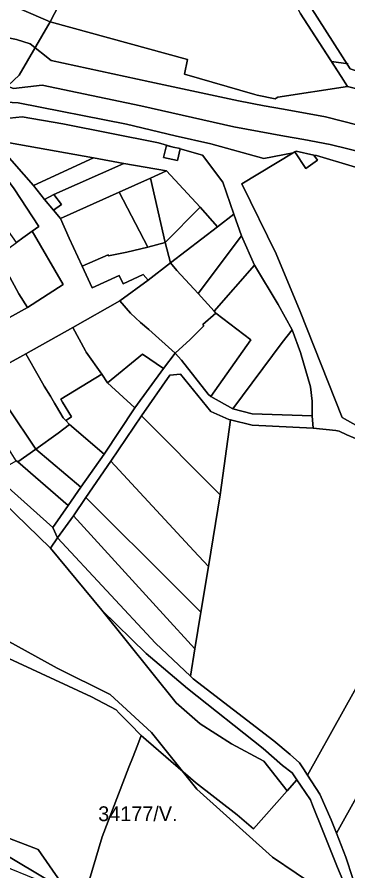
# Model space of a CAD drawing. Extents: x -545779 to -541342, y -1153413 to -1149956.
# Drawn here: x -543702.6 to -543590.9, y -1151443.3 to -1151154.8 of the extents above; entities that cross this region are included whole.
import ezdxf

# ---------------------------------------------------------------- set-up
doc = ezdxf.new("R2010")
doc.units = 0
for name, color, linetype in [('95560013', 7, 'Continuous'), ('95590013', 7, 'Continuous'), ('95600013', 7, 'Continuous'), ('95610013', 7, 'Continuous'), ('95630013', 7, 'Continuous'), ('95640013', 7, 'Continuous'), ('95660013', 7, 'Continuous')]:
    doc.layers.add(name, color=color, linetype=linetype)

msp = doc.modelspace()

# ---------------------------------------------------------------- linework, layer by layer
at = {"layer": '95560013'}
for points in [[(-543426.69, -1151032.45), (-543416.26, -1151059.6), (-543408.67, -1151071.25), (-543550.86, -1151185.35), (-543553.59, -1151184.67), (-543590.14, -1151172.28), (-543603.89, -1151150.79), (-543516.57, -1151080.72), (-543429.25, -1151010.65)], [(-543691.29, -1151334.17), (-543673.94, -1151355.22), (-543648.95, -1151386.43), (-543640.79, -1151393.58), (-543630.21, -1151400.33), (-543619.37, -1151406.18), (-543611.49, -1151416.21), (-543622.76, -1151429.01), (-543628.36, -1151424.32), (-543642.34, -1151413.36), (-543660.7, -1151397.48), (-543664.49, -1151393.61), (-543664.86, -1151393.23), (-543668.09, -1151389.92), (-543669.09, -1151388.9), (-543677.42, -1151384.4), (-543739.44, -1151355.73), (-543734.37, -1151340.55), (-543723.18, -1151345.39), (-543718.04, -1151333.17), (-543708.47, -1151320.29), (-543707.2, -1151318.74)], [(-543551.98, -1151332.36), (-543550.87, -1151334.45), (-543548.07, -1151339.72), (-543546.41, -1151342.35), (-543546.06, -1151342.91), (-543594.77, -1151430.54), (-543596.55, -1151425.99), (-543600.47, -1151417.38), (-543604.56, -1151410.97), (-543556.48, -1151324.47), (-543555.16, -1151326.78)], [(-543546.06, -1151342.91), (-543543.88, -1151346.35), (-543541.07, -1151350.8), (-543534.97, -1151358.76), (-543586.01, -1151450.59), (-543589.23, -1151445.86), (-543591.62, -1151438.6), (-543594.77, -1151430.54)]]:
    msp.add_lwpolyline(points, close=True, dxfattribs=at)
msp.add_lwpolyline([(-543556.48, -1151324.47), (-543604.56, -1151410.97), (-543605.95, -1151408.8), (-543607.27, -1151406.73), (-543610.39, -1151403.99), (-543615.92, -1151399.29), (-543643.15, -1151378.33), (-543644.09, -1151377.44), (-543642.58, -1151368.24), (-543640.56, -1151355.87), (-543638.03, -1151340.4), (-543634.06, -1151316.17), (-543630.6, -1151290.91), (-543623.22, -1151292.69), (-543602.72, -1151293.72), (-543595.06, -1151294.52), (-543593.88, -1151294.64), (-543591.36, -1151295.92), (-543582.77, -1151299.49)], dxfattribs=at)
at = {"layer": '95590013'}
for points in [[(-543707.45, -1151199.51), (-543705.09, -1151197.25), (-543676.75, -1151202.34), (-543696.99, -1151211.72), (-543707.61, -1151199.67)], [(-543690.15, -1151214.69), (-543693.35, -1151216.4), (-543696.99, -1151211.72), (-543676.75, -1151202.34), (-543666.57, -1151204.23)], [(-543657.58, -1151209.21), (-543668.11, -1151213.94), (-543687.97, -1151222.83), (-543690.31, -1151219.98), (-543687.61, -1151218.1), (-543690.15, -1151214.69), (-543666.57, -1151204.23), (-543652.11, -1151206.75)], [(-543657.58, -1151209.21), (-543652.11, -1151206.75), (-543640.81, -1151219.02), (-543652.58, -1151230.91)], [(-543658.5, -1151232.51), (-543668.11, -1151213.94), (-543657.58, -1151209.21), (-543652.58, -1151230.91)], [(-543640.81, -1151219.02), (-543634.91, -1151225.67), (-543650.86, -1151237.82), (-543652.58, -1151230.91)], [(-543650.86, -1151237.82), (-543634.91, -1151225.67), (-543629.48, -1151221.37), (-543626.8, -1151228.65), (-543641.53, -1151248.13), (-543648.65, -1151240.41)], [(-543613.18, -1151264.7), (-543609.74, -1151260.46), (-543606.96, -1151268.13), (-543603.6, -1151279.66), (-543603.04, -1151284.54), (-543603.04, -1151289.47), (-543623.3, -1151288.83), (-543629.79, -1151287.1)], [(-543660.31, -1151268.64), (-543653.13, -1151273.5), (-543662.86, -1151286.76), (-543672.1, -1151278.36)], [(-543662.86, -1151286.76), (-543673.25, -1151302.44), (-543684.87, -1151292.42), (-543686.16, -1151291.06), (-543684.23, -1151289.85), (-543687.24, -1151284.9), (-543687.86, -1151283.9), (-543673.96, -1151275.39), (-543672.1, -1151278.36)], [(-543631.15, -1151290.78), (-543630.6, -1151290.91), (-543634.06, -1151316.17), (-543634.47, -1151315.75), (-543660.58, -1151289.47), (-543651.02, -1151275.79), (-543647.44, -1151275.49), (-543637.15, -1151288.1)], [(-543634.47, -1151315.75), (-543634.06, -1151316.17), (-543638.03, -1151340.4), (-543642.93, -1151335.1), (-543670.97, -1151304.78), (-543660.58, -1151289.47)], [(-543684.87, -1151292.42), (-543673.25, -1151302.44), (-543681.02, -1151313.61), (-543696.27, -1151300.72), (-543688.77, -1151295.37)], [(-543696.27, -1151300.72), (-543681.02, -1151313.61), (-543685.3, -1151319.77), (-543702.38, -1151305.07)], [(-543702.87, -1151304.68), (-543702.38, -1151305.07), (-543685.3, -1151319.77), (-543690.49, -1151327.2), (-543709.95, -1151309.86), (-543710.37, -1151308.95)], [(-543638.03, -1151340.4), (-543640.56, -1151355.87), (-543648.94, -1151347.49), (-543679.35, -1151317.1), (-543670.97, -1151304.78), (-543642.93, -1151335.1)], [(-543648.94, -1151347.49), (-543640.56, -1151355.87), (-543642.58, -1151368.24), (-543653.3, -1151356.49), (-543683.56, -1151323.3), (-543679.35, -1151317.1)], [(-543688.98, -1151330.77), (-543688.08, -1151329.53), (-543683.56, -1151323.3), (-543653.3, -1151356.49), (-543642.58, -1151368.24), (-543644.09, -1151377.44), (-543655.85, -1151366.32)]]:
    msp.add_lwpolyline(points, close=True, dxfattribs=at)
at = {"layer": '95600013'}
msp.add_lwpolyline([(-543664.49, -1151393.61), (-543660.7, -1151397.48), (-543661.86, -1151400.51), (-543663.64, -1151405.14), (-543664.82, -1151408.21), (-543673.88, -1151431.71), (-543679.37, -1151450.34), (-543682.23, -1151449.41), (-543683.51, -1151448.99), (-543692.85, -1151445.93), (-543769.18, -1151400.33), (-543759.62, -1151391.46), (-543753.2, -1151381.33), (-543752.52, -1151379.28), (-543751.06, -1151374.9), (-543743.07, -1151354.05), (-543739.44, -1151355.73), (-543677.42, -1151384.4), (-543669.09, -1151388.9), (-543668.09, -1151389.92), (-543664.86, -1151393.23)], close=True, dxfattribs=at)
at = {"layer": '95610013'}
msp.add_lwpolyline([(-543633.18, -1151210.51), (-543629.48, -1151221.37), (-543634.91, -1151225.67), (-543640.81, -1151219.02), (-543652.11, -1151206.75), (-543666.57, -1151204.23), (-543676.75, -1151202.34), (-543705.09, -1151197.25), (-543712.86, -1151196.79), (-543710.44, -1151192.02), (-543709.48, -1151189.44), (-543700.87, -1151188.52), (-543687.14, -1151190.91), (-543654.84, -1151197.32), (-543649.92, -1151198.7), (-543652.18, -1151198.19), (-543653.23, -1151202.2), (-543648.48, -1151203.27), (-543647.59, -1151199.35), (-543639.96, -1151201.49)], close=True, dxfattribs=at)
msp.add_lwpolyline([(-543679.37, -1151450.34), (-543673.88, -1151431.71), (-543664.82, -1151408.21), (-543663.64, -1151405.14), (-543661.86, -1151400.51), (-543660.7, -1151397.48), (-543642.34, -1151413.36), (-543628.36, -1151424.32), (-543622.76, -1151429.01), (-543611.49, -1151416.21), (-543608.2, -1151412.48), (-543607, -1151414.28), (-543603.62, -1151419.3), (-543602.89, -1151421.09), (-543599.41, -1151429.72), (-543594.46, -1151442.1), (-543591.78, -1151448.59)], dxfattribs=at)
at = {"layer": '95630013'}
for points in [[(-543904.45, -1151081.5), (-543875.92, -1151102.77), (-543852.01, -1151119.39), (-543836.64, -1151127.19), (-543820.44, -1151131.33), (-543791.01, -1151135.61), (-543774.37, -1151139.55), (-543759.44, -1151144.59), (-543728.11, -1151156.46), (-543704.49, -1151161.98), (-543702.79, -1151162.38), (-543698.15, -1151163.86), (-543691.06, -1151169.41), (-543657.83, -1151176.71), (-543627.82, -1151183.14), (-543619.19, -1151184.73), (-543612.66, -1151185.94), (-543598.49, -1151188.54), (-543548.68, -1151201.25)], [(-543551.46, -1151209.01), (-543596.99, -1151197.82), (-543605.86, -1151196.19), (-543612.4, -1151194.99), (-543629.42, -1151191.86), (-543660.77, -1151184.75), (-543694.1, -1151177.77), (-543703.84, -1151178.88), (-543707.99, -1151177.29), (-543709.68, -1151176.38), (-543730.51, -1151165.23), (-543762.49, -1151152.65), (-543776.19, -1151147.43), (-543792.55, -1151143.69), (-543819.74, -1151138.33), (-543838.2, -1151135.78), (-543856.8, -1151126.79), (-543880.87, -1151109.45), (-543909.38, -1151087.89)]]:
    msp.add_lwpolyline(points, dxfattribs=at)
at = {"layer": '95640013'}
for points in [[(-543914.79, -1151053.54), (-543883.76, -1151079.27), (-543853.83, -1151099.45), (-543832.05, -1151111.38), (-543803.43, -1151116.87), (-543766.25, -1151127.49), (-543729.27, -1151141.61), (-543705.29, -1151150.15), (-543703.3, -1151146.24), (-543702.64, -1151146.72), (-543700.92, -1151151.1), (-543701.13, -1151152.25), (-543691.46, -1151156.42), (-543645.1, -1151169.14), (-543646.12, -1151174.04), (-543622.39, -1151180.97), (-543621.56, -1151181.15), (-543615.46, -1151182.44), (-543615.13, -1151182.21), (-543614.55, -1151181.8), (-543591.06, -1151178.24), (-543474.99, -1151206.7)], [(-543548.68, -1151201.25), (-543598.49, -1151188.54), (-543612.66, -1151185.94), (-543619.19, -1151184.73), (-543627.82, -1151183.14), (-543657.83, -1151176.71), (-543691.06, -1151169.41), (-543698.15, -1151163.86), (-543702.79, -1151162.38), (-543704.49, -1151161.98), (-543728.11, -1151156.46), (-543759.44, -1151144.59), (-543774.37, -1151139.55), (-543791.01, -1151135.61), (-543820.44, -1151131.33), (-543836.64, -1151127.19), (-543852.01, -1151119.39), (-543875.92, -1151102.77), (-543904.45, -1151081.5)], [(-543909.38, -1151087.89), (-543880.87, -1151109.45), (-543856.8, -1151126.79), (-543838.2, -1151135.78), (-543819.74, -1151138.33), (-543792.55, -1151143.69), (-543776.19, -1151147.43), (-543762.49, -1151152.65), (-543730.51, -1151165.23), (-543709.68, -1151176.38), (-543707.99, -1151177.29), (-543703.84, -1151178.88), (-543694.1, -1151177.77), (-543660.77, -1151184.75), (-543629.42, -1151191.86), (-543612.4, -1151194.99), (-543605.86, -1151196.19), (-543596.99, -1151197.82), (-543551.46, -1151209.01)], [(-543607.02, -1151153.49), (-543593.23, -1151174.88), (-543591.06, -1151178.24), (-543614.55, -1151181.8), (-543615.13, -1151182.21), (-543615.46, -1151182.44), (-543621.56, -1151181.15), (-543622.39, -1151180.97), (-543646.12, -1151174.04), (-543645.1, -1151169.14), (-543691.46, -1151156.42), (-543682.89, -1151139.83)], [(-543553.4, -1151215.92), (-543601.53, -1151201.58), (-543602.42, -1151201.39), (-543608.46, -1151200.09), (-543608.87, -1151200.33), (-543609.43, -1151200.65), (-543619.29, -1151202.61), (-543637.18, -1151197.56), (-543649.23, -1151194.95), (-543665.68, -1151191), (-543702.17, -1151183.73), (-543706.27, -1151183.57), (-543710.63, -1151183.4), (-543714.64, -1151182), (-543722.54, -1151178.99), (-543736.15, -1151174.3), (-543749.75, -1151169.5), (-543763.41, -1151164.4), (-543777, -1151159.58), (-543787.4, -1151156.11), (-543798.93, -1151152.89)], [(-543706.27, -1151183.57), (-543702.17, -1151183.73), (-543665.68, -1151191), (-543649.23, -1151194.95), (-543637.18, -1151197.56), (-543619.29, -1151202.61), (-543609.43, -1151200.65), (-543626.78, -1151211.1), (-543615.15, -1151234.83), (-543607.08, -1151254.31), (-543592.86, -1151290.06), (-543564.09, -1151306.26)], [(-543582.77, -1151299.49), (-543591.36, -1151295.92), (-543593.88, -1151294.64), (-543595.06, -1151294.52), (-543602.72, -1151293.72), (-543603.04, -1151289.47), (-543603.04, -1151284.54), (-543603.6, -1151279.66), (-543606.96, -1151268.13), (-543609.74, -1151260.46), (-543614.45, -1151251.92), (-543622.45, -1151238.56), (-543626.8, -1151228.65), (-543629.48, -1151221.37), (-543633.18, -1151210.51), (-543639.96, -1151201.49), (-543647.59, -1151199.35), (-543647.56, -1151199.23), (-543649.92, -1151198.7), (-543654.84, -1151197.32), (-543687.14, -1151190.91), (-543700.87, -1151188.52), (-543709.48, -1151189.44)], [(-543707.61, -1151199.67), (-543696.99, -1151211.72), (-543693.35, -1151216.4), (-543690.31, -1151219.98), (-543687.97, -1151222.83), (-543684.97, -1151229.45), (-543680.64, -1151238.98), (-543677.28, -1151246.3), (-543668.09, -1151242.1), (-543666.73, -1151244.88), (-543660.02, -1151241.79), (-543658.4, -1151243.65), (-543667.96, -1151250.69), (-543683.79, -1151259.72), (-543699.65, -1151268.52), (-543712.31, -1151275.52)], [(-543564.09, -1151306.26), (-543592.86, -1151290.06), (-543607.08, -1151254.31), (-543615.15, -1151234.83), (-543626.78, -1151211.1), (-543609.43, -1151200.65), (-543608.87, -1151200.33), (-543608.46, -1151200.09), (-543602.42, -1151201.39), (-543601.53, -1151201.58), (-543553.4, -1151215.92)], [(-543709.95, -1151309.86), (-543690.49, -1151327.2), (-543688.98, -1151330.77), (-543691.29, -1151334.17), (-543707.2, -1151318.74)], [(-543591.78, -1151448.59), (-543594.46, -1151442.1), (-543599.41, -1151429.72), (-543602.89, -1151421.09), (-543603.62, -1151419.3), (-543607, -1151414.28), (-543608.2, -1151412.48), (-543609.8, -1151410.1), (-543612.97, -1151407.6), (-543619.54, -1151401.93), (-543645.13, -1151381.61), (-543659.01, -1151369.77), (-543673.94, -1151355.22), (-543691.29, -1151334.17), (-543688.98, -1151330.77), (-543655.85, -1151366.32), (-543644.09, -1151377.44), (-543643.15, -1151378.33), (-543615.92, -1151399.29), (-543610.39, -1151403.99), (-543607.27, -1151406.73), (-543605.95, -1151408.8), (-543604.56, -1151410.97), (-543600.47, -1151417.38), (-543596.55, -1151425.99), (-543594.77, -1151430.54), (-543591.62, -1151438.6), (-543589.23, -1151445.86)]]:
    msp.add_lwpolyline(points, dxfattribs=at)
for points in [[(-543591.06, -1151178.24), (-543593.23, -1151174.88), (-543607.02, -1151153.49), (-543634.9, -1151097.4), (-543628.2, -1151092.28), (-543630.2, -1151097.88), (-543624.3, -1151109.73), (-543603.89, -1151150.79), (-543590.14, -1151172.28), (-543553.59, -1151184.67), (-543550.86, -1151185.35), (-543521.25, -1151192.65), (-543475.14, -1151204.03), (-543448.24, -1151210.67), (-543423.83, -1151216.7), (-543340.81, -1151237.2), (-543325.56, -1151240.65), (-543225.5, -1151263.28), (-543213.98, -1151267.2), (-543204.67, -1151270.37), (-543341.53, -1151239.59), (-543425.84, -1151218.75), (-543474.99, -1151206.7)], [(-543690.45, -1151132.16), (-543682.89, -1151139.83), (-543691.46, -1151156.42), (-543701.13, -1151152.25), (-543699.75, -1151148.74)], [(-543649.92, -1151198.7), (-543647.56, -1151199.23), (-543647.59, -1151199.35), (-543648.48, -1151203.27), (-543653.23, -1151202.2), (-543652.18, -1151198.19)], [(-543687.02, -1151245.12), (-543697.47, -1151227.07), (-543695.27, -1151225.57), (-543703.52, -1151212.82), (-543704.8, -1151211.08), (-543707.93, -1151206.67), (-543715.75, -1151213.76), (-543722.05, -1151219.55), (-543734.92, -1151231.03), (-543745.16, -1151239.53), (-543747.71, -1151241.69), (-543746.82, -1151242.67), (-543743.07, -1151247.07), (-543743.22, -1151247.62), (-543735.7, -1151253.66), (-543732.87, -1151256.11), (-543729.14, -1151259.03), (-543729.01, -1151258.86), (-543723.13, -1151265.27), (-543711.35, -1151259.67), (-543699.04, -1151252.91)], [(-543707.93, -1151206.67), (-543704.8, -1151211.08), (-543703.52, -1151212.82), (-543695.27, -1151225.57), (-543697.47, -1151227.07), (-543700.61, -1151229.38), (-543702.77, -1151230.98), (-543708.21, -1151223.27), (-543712.06, -1151217.91), (-543715.75, -1151213.76)], [(-543693.35, -1151216.4), (-543690.15, -1151214.69), (-543687.61, -1151218.1), (-543690.31, -1151219.98)], [(-543665.56, -1151234.23), (-543671.68, -1151235.44), (-543671.8, -1151235.17), (-543680.64, -1151238.98), (-543684.97, -1151229.45), (-543687.97, -1151222.83), (-543668.11, -1151213.94), (-543658.5, -1151232.51)], [(-543705.31, -1151232.84), (-543702.77, -1151230.98), (-543700.61, -1151229.38), (-543697.47, -1151227.07), (-543687.02, -1151245.12), (-543699.04, -1151252.91), (-543702.04, -1151248.25), (-543708.93, -1151235.56)], [(-543636.05, -1151254.17), (-543641.53, -1151248.13), (-543626.8, -1151228.65), (-543622.45, -1151238.56)], [(-543650.86, -1151237.82), (-543658.4, -1151243.65), (-543660.02, -1151241.79), (-543666.73, -1151244.88), (-543668.09, -1151242.1), (-543677.28, -1151246.3), (-543680.64, -1151238.98), (-543671.8, -1151235.17), (-543671.68, -1151235.44), (-543665.56, -1151234.23), (-543658.5, -1151232.51), (-543652.58, -1151230.91)], [(-543708.93, -1151235.56), (-543702.04, -1151248.25), (-543699.04, -1151252.91), (-543711.35, -1151259.67), (-543719.29, -1151243.33), (-543714.35, -1151239.93), (-543713.95, -1151239.5), (-543709.2, -1151235.77)], [(-543639.58, -1151259.09), (-543644.23, -1151263.73), (-543649.28, -1151268.29), (-543658.15, -1151260.31), (-543660.95, -1151258), (-543664.32, -1151254.81), (-543667.96, -1151250.69), (-543658.4, -1151243.65), (-543650.86, -1151237.82), (-543648.65, -1151240.41), (-543641.53, -1151248.13), (-543636.05, -1151254.17), (-543635.52, -1151254.77), (-543639.88, -1151258.66)], [(-543614.45, -1151251.92), (-543609.74, -1151260.46), (-543613.18, -1151264.7), (-543629.79, -1151287.1), (-543637.17, -1151283.03), (-543623.71, -1151263.88), (-543635.52, -1151254.77), (-543636.05, -1151254.17), (-543622.45, -1151238.56)], [(-543672.1, -1151278.36), (-543673.96, -1151275.39), (-543679.27, -1151267.97), (-543679.53, -1151267.5), (-543683.79, -1151259.72), (-543667.96, -1151250.69), (-543664.32, -1151254.81), (-543660.95, -1151258), (-543658.15, -1151260.31), (-543649.28, -1151268.29), (-543653.13, -1151273.5), (-543660.31, -1151268.64)], [(-543635.52, -1151254.77), (-543623.71, -1151263.88), (-543637.17, -1151283.03), (-543638.11, -1151282.16), (-543647.06, -1151270.71), (-543649.28, -1151268.29), (-543644.23, -1151263.73), (-543639.58, -1151259.09), (-543639.88, -1151258.66)], [(-543689.27, -1151286.35), (-543689.95, -1151285.19), (-543691.31, -1151282.91), (-543693.39, -1151279.48), (-543695.05, -1151276.63), (-543699.65, -1151268.52), (-543683.79, -1151259.72), (-543679.53, -1151267.5), (-543679.27, -1151267.97), (-543673.96, -1151275.39), (-543687.86, -1151283.9), (-543687.24, -1151284.9), (-543684.23, -1151289.85), (-543686.16, -1151291.06), (-543687, -1151290.18)], [(-543629.79, -1151287.1), (-543623.3, -1151288.83), (-543603.04, -1151289.47), (-543602.72, -1151293.72), (-543623.22, -1151292.69), (-543630.6, -1151290.91), (-543631.15, -1151290.78), (-543637.15, -1151288.1), (-543647.44, -1151275.49), (-543651.02, -1151275.79), (-543660.58, -1151289.47), (-543670.97, -1151304.78), (-543679.35, -1151317.1), (-543683.56, -1151323.3), (-543688.08, -1151329.53), (-543688.98, -1151330.77), (-543690.49, -1151327.2), (-543685.3, -1151319.77), (-543681.02, -1151313.61), (-543673.25, -1151302.44), (-543662.86, -1151286.76), (-543653.13, -1151273.5), (-543649.28, -1151268.29), (-543647.06, -1151270.71), (-543638.11, -1151282.16), (-543637.17, -1151283.03)], [(-543689.27, -1151286.35), (-543687, -1151290.18), (-543686.16, -1151291.06), (-543684.87, -1151292.42), (-543688.77, -1151295.37), (-543696.27, -1151300.72), (-543705.61, -1151286.8), (-543709.19, -1151280.65), (-543712.31, -1151275.52), (-543699.65, -1151268.52), (-543695.05, -1151276.63), (-543693.39, -1151279.48), (-543691.31, -1151282.91), (-543689.95, -1151285.19)], [(-543709.19, -1151280.65), (-543705.61, -1151286.8), (-543696.27, -1151300.72), (-543702.38, -1151305.07), (-543702.87, -1151304.68), (-543707.4, -1151297.52), (-543715.27, -1151285.61), (-543715.48, -1151284.97), (-543718.88, -1151279.16), (-543712.31, -1151275.52)], [(-543609.8, -1151410.1), (-543608.2, -1151412.48), (-543611.49, -1151416.21), (-543619.37, -1151406.18), (-543630.21, -1151400.33), (-543640.79, -1151393.58), (-543648.95, -1151386.43), (-543673.94, -1151355.22), (-543659.01, -1151369.77), (-543645.13, -1151381.61), (-543619.54, -1151401.93), (-543612.97, -1151407.6)], [(-543743.38, -1151424.94), (-543769.18, -1151400.33), (-543692.85, -1151445.93), (-543683.51, -1151448.99), (-543682.23, -1151449.41), (-543679.37, -1151450.34), (-543680.2, -1151452.67), (-543684.44, -1151450.94), (-543719.33, -1151436.66)]]:
    msp.add_lwpolyline(points, close=True, dxfattribs=at)
at = {"layer": '95660013'}
for points in [[(-543590.84, -1151170.626), (-543596.525, -1151169.769), (-543607.02, -1151153.49), (-543634.9, -1151097.4), (-543638.05, -1151091.07), (-543608.97, -1151067.59), (-543670.14, -1151020.9), (-543709.38, -1150990.96), (-543755.27, -1150957.07), (-543776.22, -1150934.68), (-543776, -1150934.43), (-543756.47, -1150911.73), (-543830.4, -1150868.97), (-543831.46, -1150868.11), (-543865.01, -1150840.92), (-543870.95, -1150836.1), (-543886.65, -1150823.39), (-543889.76, -1150820.87), (-543912.05, -1150802.81), (-543980.18, -1150755.91), (-543984.63, -1150753.63), (-544024.7, -1150733.15)], [(-543682.89, -1151139.83), (-543691.46, -1151156.42), (-543701.849, -1151174.453), (-543720.987, -1151192.317), (-543743.956, -1151224.216), (-543750, -1151230.018), (-543775.855, -1151254.839), (-543798.822, -1151272.703), (-543806.478, -1151271.427), (-543810.305, -1151272.703), (-543823.066, -1151286.739), (-543833.272, -1151293.118), (-543844.757, -1151294.394), (-543858.792, -1151289.29), (-543876.656, -1151276.531), (-543893.243, -1151265.047), (-543925.143, -1151240.804)], [(-543607.02, -1151153.49), (-543596.525, -1151169.769), (-543593.23, -1151174.88), (-543591.06, -1151178.24), (-543614.55, -1151181.8), (-543615.13, -1151182.21), (-543615.46, -1151182.44), (-543621.56, -1151181.15), (-543622.39, -1151180.97), (-543646.12, -1151174.04), (-543645.1, -1151169.14), (-543691.46, -1151156.42), (-543682.89, -1151139.83)], [(-543720.987, -1151192.317), (-543701.849, -1151174.453), (-543691.46, -1151156.42), (-543645.1, -1151169.14), (-543646.12, -1151174.04), (-543622.39, -1151180.97), (-543621.56, -1151181.15), (-543615.46, -1151182.44), (-543615.13, -1151182.21), (-543614.55, -1151181.8), (-543591.06, -1151178.24), (-543593.23, -1151174.88), (-543596.525, -1151169.769), (-543590.84, -1151170.626)], [(-543553.4, -1151215.92), (-543601.53, -1151201.58), (-543602.42, -1151201.39), (-543601.26, -1151203.14), (-543605.15, -1151205.96), (-543608.87, -1151200.33), (-543609.43, -1151200.65), (-543626.78, -1151211.1), (-543615.15, -1151234.83), (-543607.08, -1151254.31), (-543592.86, -1151290.06), (-543564.09, -1151306.26)], [(-543564.09, -1151306.26), (-543592.86, -1151290.06), (-543607.08, -1151254.31), (-543615.15, -1151234.83), (-543626.78, -1151211.1), (-543609.43, -1151200.65), (-543608.87, -1151200.33), (-543605.15, -1151205.96), (-543601.26, -1151203.14), (-543602.42, -1151201.39), (-543601.53, -1151201.58), (-543553.4, -1151215.92)], [(-543925.143, -1151240.804), (-543893.243, -1151265.047), (-543876.656, -1151276.531), (-543858.792, -1151289.29), (-543844.757, -1151294.394), (-543833.272, -1151293.118), (-543823.066, -1151286.739), (-543810.305, -1151272.703), (-543806.478, -1151271.427), (-543798.822, -1151272.703), (-543761.818, -1151296.946), (-543750, -1151302.433), (-543726.092, -1151313.534), (-543713.333, -1151323.742), (-543726.092, -1151354.365), (-543742.68, -1151347.985), (-543750, -1151362.24), (-543766.923, -1151395.196), (-543750, -1151406.8), (-543722.263, -1151425.819), (-543695.469, -1151436.027), (-543683.985, -1151452.614)], [(-543584.46, -1151460.27), (-543616.357, -1151438.578), (-543641.879, -1151415.611), (-543657.189, -1151396.472), (-543671.226, -1151383.712), (-543689.088, -1151374.78), (-543726.092, -1151354.365)]]:
    msp.add_lwpolyline(points, dxfattribs=at)
msp.add_lwpolyline([(-543552.561, -1151473.03), (-543548.647, -1151474.591), (-543554.44, -1151493.44), (-543557.95, -1151504.85), (-543561.493, -1151504.929), (-543579.355, -1151494.721), (-543611.254, -1151479.409), (-543641.879, -1151466.65), (-543661.018, -1151462.822), (-543675.053, -1151457.718), (-543683.985, -1151452.614), (-543695.469, -1151436.027), (-543722.263, -1151425.819), (-543750, -1151406.8), (-543766.923, -1151395.196), (-543750, -1151362.24), (-543742.68, -1151347.985), (-543726.092, -1151354.365), (-543689.088, -1151374.78), (-543671.226, -1151383.712), (-543657.189, -1151396.472), (-543641.879, -1151415.611), (-543616.357, -1151438.578), (-543584.46, -1151460.27)], close=True, dxfattribs=at)

# ---------------------------------------------------------------- texts
msp.add_text('34177/V.', height=5, rotation=0, dxfattribs=at).set_placement((-543675.207, -1151426.457))

doc.saveas('drawing.dxf')
